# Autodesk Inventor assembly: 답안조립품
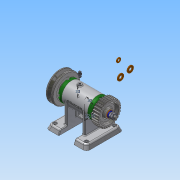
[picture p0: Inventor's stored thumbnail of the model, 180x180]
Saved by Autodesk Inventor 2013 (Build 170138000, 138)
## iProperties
Created: 2008-12
Part Number: 답안조립품
Document SubType Name: Assembly
Designer: Administrator
Author: Administrator
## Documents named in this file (16)
- C:\Users\Administrator\Desktop\460708V1011\답안조립품.iam
- C:\Users\Administrator\Desktop\460708V1011\본체.ipt
- C:\Users\Administrator\Desktop\460708V1011\V벨트풀리.ipt
- C:\Users\Administrator\Desktop\460708V1011\너트 M 8.ipt
- C:\Users\Administrator\Desktop\460708V1011\니플 M 6 x 0.75.ipt
- C:\Users\Administrator\Desktop\460708V1011\베어링 15 x 32 x 9.ipt
- C:\Users\Administrator\Desktop\460708V1011\볼트 M 6 x 8.ipt
- C:\Users\Administrator\Desktop\460708V1011\볼트 M4 x 12.ipt
- C:\Users\Administrator\Desktop\460708V1011\스퍼기어.ipt
- C:\Users\Administrator\Desktop\460708V1011\스프링와셔 8.ipt
- C:\Users\Administrator\Desktop\460708V1011\오일 실 15 25 7.ipt
- C:\Users\Administrator\Desktop\460708V1011\와셔 6x11.5.ipt
- C:\Users\Administrator\Desktop\460708V1011\와셔 8x17.ipt
- C:\Users\Administrator\Desktop\460708V1011\축.ipt
- C:\Users\Administrator\Desktop\460708V1011\커버.ipt
- C:\Users\Administrator\Desktop\460708V1011\키 3 x 3 x 12.ipt
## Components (11 placed, 3 different names)
1. V벨트풀리:1
2. KS B 2023 6002 - 15 x 32 x 9:1
3. KS B 2023 6002 - 15 x 32 x 9:2
4. ISO 4762 M4 x 12:2
5. ISO 4762 M4 x 12:1
6. ISO 4762 M4 x 12:3
7. ISO 4762 M4 x 12:4
8. ISO 4762 M4 x 12:5
9. ISO 4762 M4 x 12:6
10. ISO 4762 M4 x 12:7
11. ISO 4762 M4 x 12:8
